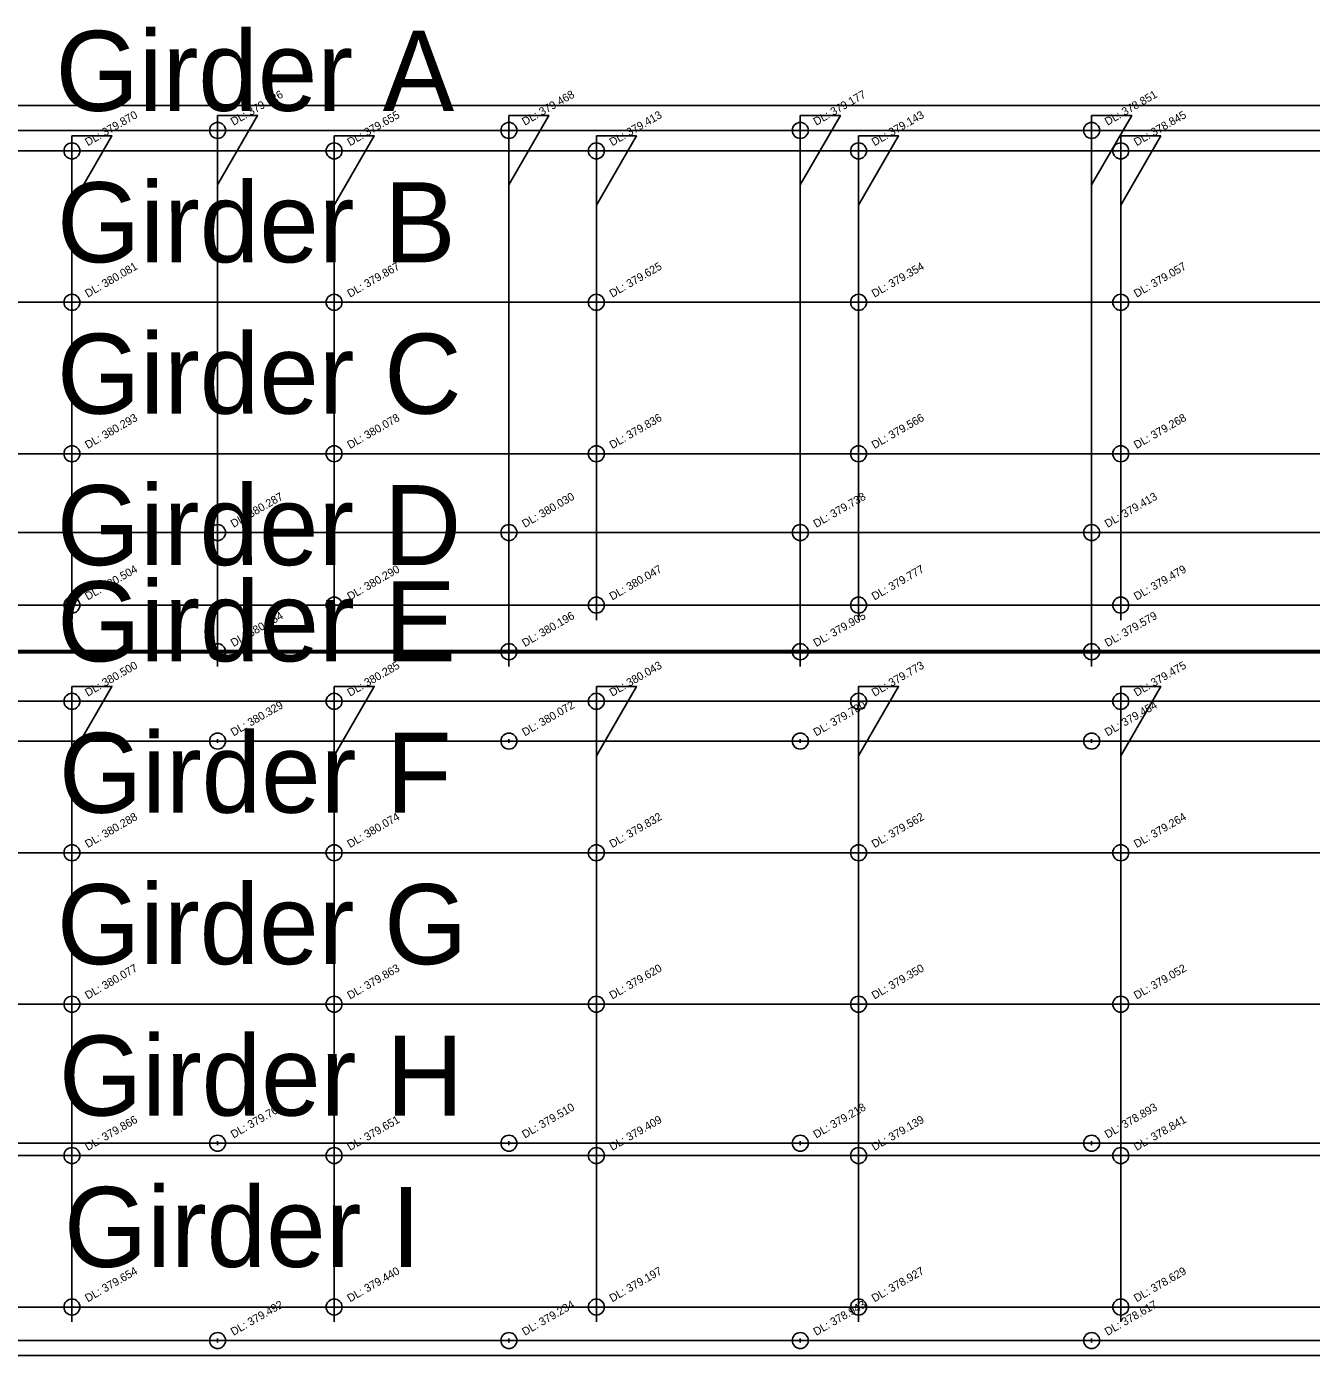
# Model space of a CAD drawing. Extents: x 100440 to 101111, y 50226 to 50315.
# Drawn here: x 100774.5 to 100860.7, y 50225.9 to 50315.1 of the extents above; entities that cross this region are included whole.
import ezdxf

# ---------------------------------------------------------------- set-up
doc = ezdxf.new("R2010")
doc.units = 0
for name, color, linetype in [('Level 1', 7, 'Continuous'), ('Level 10', 7, 'Continuous'), ('Level 23', 7, 'Continuous')]:
    doc.layers.add(name, color=color, linetype=linetype)

msp = doc.modelspace()

# ---------------------------------------------------------------- linework, layer by layer
at = {"layer": 'Level 1'}
for p, q in [((100559.504, 50306.768), (101034.504, 50306.768)), ((100559.504, 50296.601), (101034.504, 50296.601)), ((100559.504, 50286.435), (101034.504, 50286.435)), ((100559.504, 50276.268), (101034.504, 50276.268)), ((100559.504, 50269.81), (101034.504, 50269.81)), ((100559.504, 50259.643), (101034.504, 50259.643)), ((100559.504, 50249.476), (101034.504, 50249.476)), ((100559.504, 50239.31), (101034.504, 50239.31)), ((100559.504, 50229.143), (101034.504, 50229.143))]:
    msp.add_line(p, q, dxfattribs=at)
at = {"layer": 'Level 10'}
for p, q in [((100787.282, 50273.268), (100787.282, 50273.018)), ((100806.837, 50273.268), (100806.837, 50273.018)), ((100826.393, 50273.268), (100826.393, 50273.018)), ((100845.949, 50273.268), (100845.949, 50273.018)), ((100787.282, 50267.268), (100787.282, 50267.018)), ((100806.837, 50267.268), (100806.837, 50267.018)), ((100826.393, 50267.268), (100826.393, 50267.018)), ((100845.949, 50267.268), (100845.949, 50267.018)), ((100787.282, 50240.268), (100787.282, 50240.018)), ((100806.837, 50240.268), (100806.837, 50240.018)), ((100826.393, 50240.268), (100826.393, 50240.018)), ((100845.949, 50240.268), (100845.949, 50240.018)), ((100787.282, 50227.018), (100787.282, 50226.768)), ((100806.837, 50227.018), (100806.837, 50226.768)), ((100826.393, 50227.018), (100826.393, 50226.768)), ((100845.949, 50227.018), (100845.949, 50226.768))]:
    msp.add_line(p, q, dxfattribs=at)
for points in [[(100787.282, 50309.143), (100787.282, 50272.143)], [(100787.282, 50304.489), (100789.969, 50309.143), (100787.282, 50309.143)], [(100806.837, 50309.143), (100806.837, 50272.143)], [(100806.837, 50304.489), (100809.524, 50309.143), (100806.837, 50309.143)], [(100826.393, 50309.143), (100826.393, 50272.143)], [(100826.393, 50304.489), (100829.08, 50309.143), (100826.393, 50309.143)], [(100845.949, 50309.143), (100845.949, 50272.143)], [(100845.949, 50304.489), (100848.635, 50309.143), (100845.949, 50309.143)], [(100777.504, 50307.768), (100777.504, 50275.268)], [(100777.504, 50303.114), (100780.191, 50307.768), (100777.504, 50307.768)], [(100795.104, 50307.768), (100795.104, 50275.268)], [(100795.104, 50303.114), (100797.791, 50307.768), (100795.104, 50307.768)], [(100812.704, 50307.768), (100812.704, 50275.268)], [(100812.704, 50303.114), (100815.391, 50307.768), (100812.704, 50307.768)], [(100830.304, 50307.768), (100830.304, 50275.268)], [(100830.304, 50303.114), (100832.991, 50307.768), (100830.304, 50307.768)], [(100847.904, 50307.768), (100847.904, 50275.268)], [(100847.904, 50303.114), (100850.591, 50307.768), (100847.904, 50307.768)], [(100777.504, 50270.81), (100777.504, 50228.143)], [(100777.504, 50266.156), (100780.191, 50270.81), (100777.504, 50270.81)], [(100795.104, 50270.81), (100795.104, 50228.143)], [(100795.104, 50266.156), (100797.791, 50270.81), (100795.104, 50270.81)], [(100812.704, 50270.81), (100812.704, 50228.143)], [(100812.704, 50266.156), (100815.391, 50270.81), (100812.704, 50270.81)], [(100830.304, 50270.81), (100830.304, 50228.143)], [(100830.304, 50266.156), (100832.991, 50270.81), (100830.304, 50270.81)], [(100847.904, 50270.81), (100847.904, 50228.143)], [(100847.904, 50266.156), (100850.591, 50270.81), (100847.904, 50270.81)]]:
    msp.add_lwpolyline(points, dxfattribs=at)
for centre in [(100787.282, 50308.143), (100806.837, 50308.143), (100826.393, 50308.143), (100845.949, 50308.143), (100777.504, 50306.768), (100795.104, 50306.768), (100812.704, 50306.768), (100830.304, 50306.768), (100847.904, 50306.768), (100777.504, 50296.601), (100795.104, 50296.601), (100812.704, 50296.601), (100830.304, 50296.601), (100847.904, 50296.601), (100777.504, 50286.435), (100795.104, 50286.435), (100812.704, 50286.435), (100830.304, 50286.435), (100847.904, 50286.435), (100787.282, 50281.143), (100806.837, 50281.143), (100826.393, 50281.143), (100845.949, 50281.143), (100777.504, 50276.268), (100795.104, 50276.268), (100812.704, 50276.268), (100830.304, 50276.268), (100847.904, 50276.268), (100787.282, 50273.143), (100787.282, 50273.143), (100806.837, 50273.143), (100806.837, 50273.143), (100826.393, 50273.143), (100826.393, 50273.143), (100845.949, 50273.143), (100845.949, 50273.143), (100777.504, 50269.81), (100795.104, 50269.81), (100812.704, 50269.81), (100830.304, 50269.81), (100847.904, 50269.81), (100787.282, 50267.143), (100806.837, 50267.143), (100826.393, 50267.143), (100845.949, 50267.143), (100777.504, 50259.643), (100795.104, 50259.643), (100812.704, 50259.643), (100830.304, 50259.643), (100847.904, 50259.643), (100777.504, 50249.476), (100795.104, 50249.476), (100812.704, 50249.476), (100830.304, 50249.476), (100847.904, 50249.476), (100787.282, 50240.143), (100806.837, 50240.143), (100826.393, 50240.143), (100845.949, 50240.143), (100777.504, 50239.31), (100795.104, 50239.31), (100812.704, 50239.31), (100830.304, 50239.31), (100847.904, 50239.31), (100777.504, 50229.143), (100795.104, 50229.143), (100812.704, 50229.143), (100830.304, 50229.143), (100847.904, 50229.143), (100787.282, 50226.893), (100806.837, 50226.893), (100826.393, 50226.893), (100845.949, 50226.893)]:
    msp.add_circle(centre, 0.537, dxfattribs=at)
at = {"layer": 'Level 23'}
for p, q in [((100439.554, 50309.81), (101111.484, 50309.81)), ((100439.554, 50308.143), (101111.484, 50308.143)), ((100439.554, 50281.143), (101111.484, 50281.143)), ((100439.554, 50273.226), (101111.484, 50273.226)), ((100439.554, 50273.143), (101111.484, 50273.143)), ((100448.204, 50273.143), (101107.514, 50273.143)), ((100448.204, 50273.06), (101107.514, 50273.06)), ((100448.204, 50267.143), (101107.514, 50267.143)), ((100448.204, 50240.143), (101107.514, 50240.143)), ((100448.204, 50226.893), (101107.514, 50226.893)), ((100448.204, 50225.893), (101107.514, 50225.893))]:
    msp.add_line(p, q, dxfattribs=at)

# ---------------------------------------------------------------- texts
at = {"layer": 'Level 1'}
for s, p in [('Girder A', (100776.406, 50309.455)), ('Girder B', (100776.504, 50299.288)), ('Girder C', (100776.504, 50289.121)), ('Girder D', (100776.487, 50278.955)), ('Girder E', (100776.518, 50272.496)), ('Girder F', (100776.63, 50262.33)), ('Girder G', (100776.497, 50252.163)), ('Girder H', (100776.63, 50241.996)), ('Girder I', (100776.966, 50231.83))]:
    msp.add_text(s, height=5.3733, dxfattribs=at).set_placement(p)
at = {"layer": 'Level 10'}
for s, p in [('DL: 379.177', (100827.458, 50308.448)), ('DL: 379.726', (100788.347, 50308.448)), ('DL: 379.468', (100807.902, 50308.448)), ('DL: 378.851', (100847.014, 50308.448)), ('DL: 379.870', (100778.569, 50307.073)), ('DL: 379.655', (100796.169, 50307.073)), ('DL: 379.413', (100813.769, 50307.073)), ('DL: 379.143', (100831.369, 50307.073)), ('DL: 378.845', (100848.969, 50307.073)), ('DL: 380.081', (100778.569, 50296.906)), ('DL: 379.867', (100796.169, 50296.906)), ('DL: 379.625', (100813.769, 50296.906)), ('DL: 379.354', (100831.369, 50296.906)), ('DL: 379.057', (100848.969, 50296.906)), ('DL: 380.293', (100778.569, 50286.739)), ('DL: 380.078', (100796.169, 50286.739)), ('DL: 379.836', (100813.769, 50286.739)), ('DL: 379.566', (100831.369, 50286.739)), ('DL: 379.268', (100848.969, 50286.739)), ('DL: 380.287', (100788.347, 50281.448)), ('DL: 380.030', (100807.902, 50281.448)), ('DL: 379.738', (100827.458, 50281.448)), ('DL: 379.413', (100847.014, 50281.448)), ('DL: 380.504', (100778.569, 50276.573)), ('DL: 380.290', (100796.169, 50276.573)), ('DL: 380.047', (100813.769, 50276.573)), ('DL: 379.777', (100831.369, 50276.573)), ('DL: 379.479', (100848.969, 50276.573)), ('DL: 380.454', (100788.347, 50273.448)), ('DL: 380.454', (100788.347, 50273.448)), ('DL: 380.196', (100807.902, 50273.448)), ('DL: 380.196', (100807.902, 50273.448)), ('DL: 379.905', (100827.458, 50273.448)), ('DL: 379.905', (100827.458, 50273.448)), ('DL: 379.579', (100847.014, 50273.448)), ('DL: 379.579', (100847.014, 50273.448)), ('DL: 380.500', (100778.569, 50270.114)), ('DL: 380.285', (100796.169, 50270.114)), ('DL: 379.475', (100848.969, 50270.114)), ('DL: 380.043', (100813.769, 50270.114)), ('DL: 379.773', (100831.369, 50270.114)), ('DL: 380.329', (100788.347, 50267.448)), ('DL: 380.072', (100807.902, 50267.448)), ('DL: 379.780', (100827.458, 50267.448)), ('DL: 379.454', (100847.014, 50267.448)), ('DL: 380.288', (100778.569, 50259.948)), ('DL: 380.074', (100796.169, 50259.948)), ('DL: 379.832', (100813.769, 50259.948)), ('DL: 379.562', (100831.369, 50259.948)), ('DL: 379.264', (100848.969, 50259.948)), ('DL: 380.077', (100778.569, 50249.781)), ('DL: 379.863', (100796.169, 50249.781)), ('DL: 379.620', (100813.769, 50249.781)), ('DL: 379.350', (100831.369, 50249.781)), ('DL: 379.052', (100848.969, 50249.781)), ('DL: 379.767', (100788.347, 50240.448)), ('DL: 379.510', (100807.902, 50240.448)), ('DL: 379.218', (100827.458, 50240.448)), ('DL: 378.893', (100847.014, 50240.448)), ('DL: 379.866', (100778.569, 50239.614)), ('DL: 379.651', (100796.169, 50239.614)), ('DL: 379.409', (100813.769, 50239.614)), ('DL: 379.139', (100831.369, 50239.614)), ('DL: 378.841', (100848.969, 50239.614)), ('DL: 379.654', (100778.569, 50229.448)), ('DL: 379.440', (100796.169, 50229.448)), ('DL: 379.197', (100813.769, 50229.448)), ('DL: 378.927', (100831.369, 50229.448)), ('DL: 378.629', (100848.969, 50229.448)), ('DL: 379.492', (100788.347, 50227.198)), ('DL: 379.234', (100807.902, 50227.198)), ('DL: 378.943', (100827.458, 50227.198)), ('DL: 378.617', (100847.014, 50227.198))]:
    msp.add_text(s, height=0.53732, rotation=30, dxfattribs=at).set_placement(p)

doc.saveas('drawing.dxf')
